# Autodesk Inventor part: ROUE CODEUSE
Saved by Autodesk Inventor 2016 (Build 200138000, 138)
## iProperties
Created: 2013-10
Part Number: ROUE CODEUSE
Material: Générique
Document SubType Name: Modeling
Designer: Bruno
Density: 1 g/cm^3
Appearance: Par défaut
Author: Bruno
Sending System: SolidWorks 2013
Last Author: JG
Last Saved: 2014-02-15
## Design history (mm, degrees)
feature "Enlèv. mat.-Extru.2"
node "Solide1"
